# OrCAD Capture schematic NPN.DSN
size A
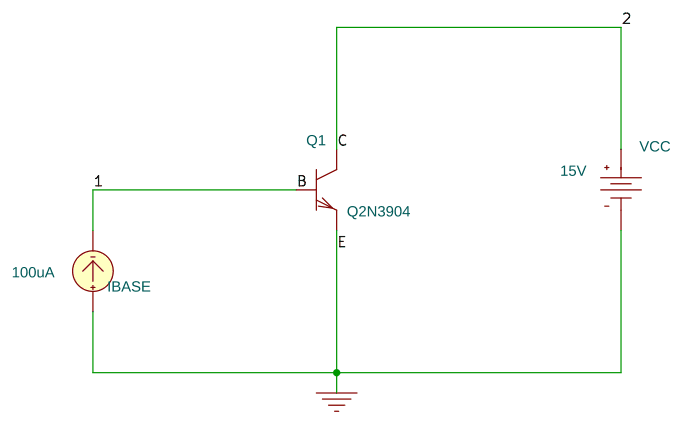
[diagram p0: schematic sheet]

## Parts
IBASE  IDC
Q1  Q2N3904  [TO92]
VCC  VDC

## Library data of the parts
IBASE = IDC: DC: 100uA
Q1 = Q2N3904
VCC = VDC: DC: 15V

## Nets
0: IBASE.1(+) Q1.1(e) VCC.1(-)
1: IBASE.2(-) Q1.2(b)
2: Q1.3(c) VCC.0(+)
